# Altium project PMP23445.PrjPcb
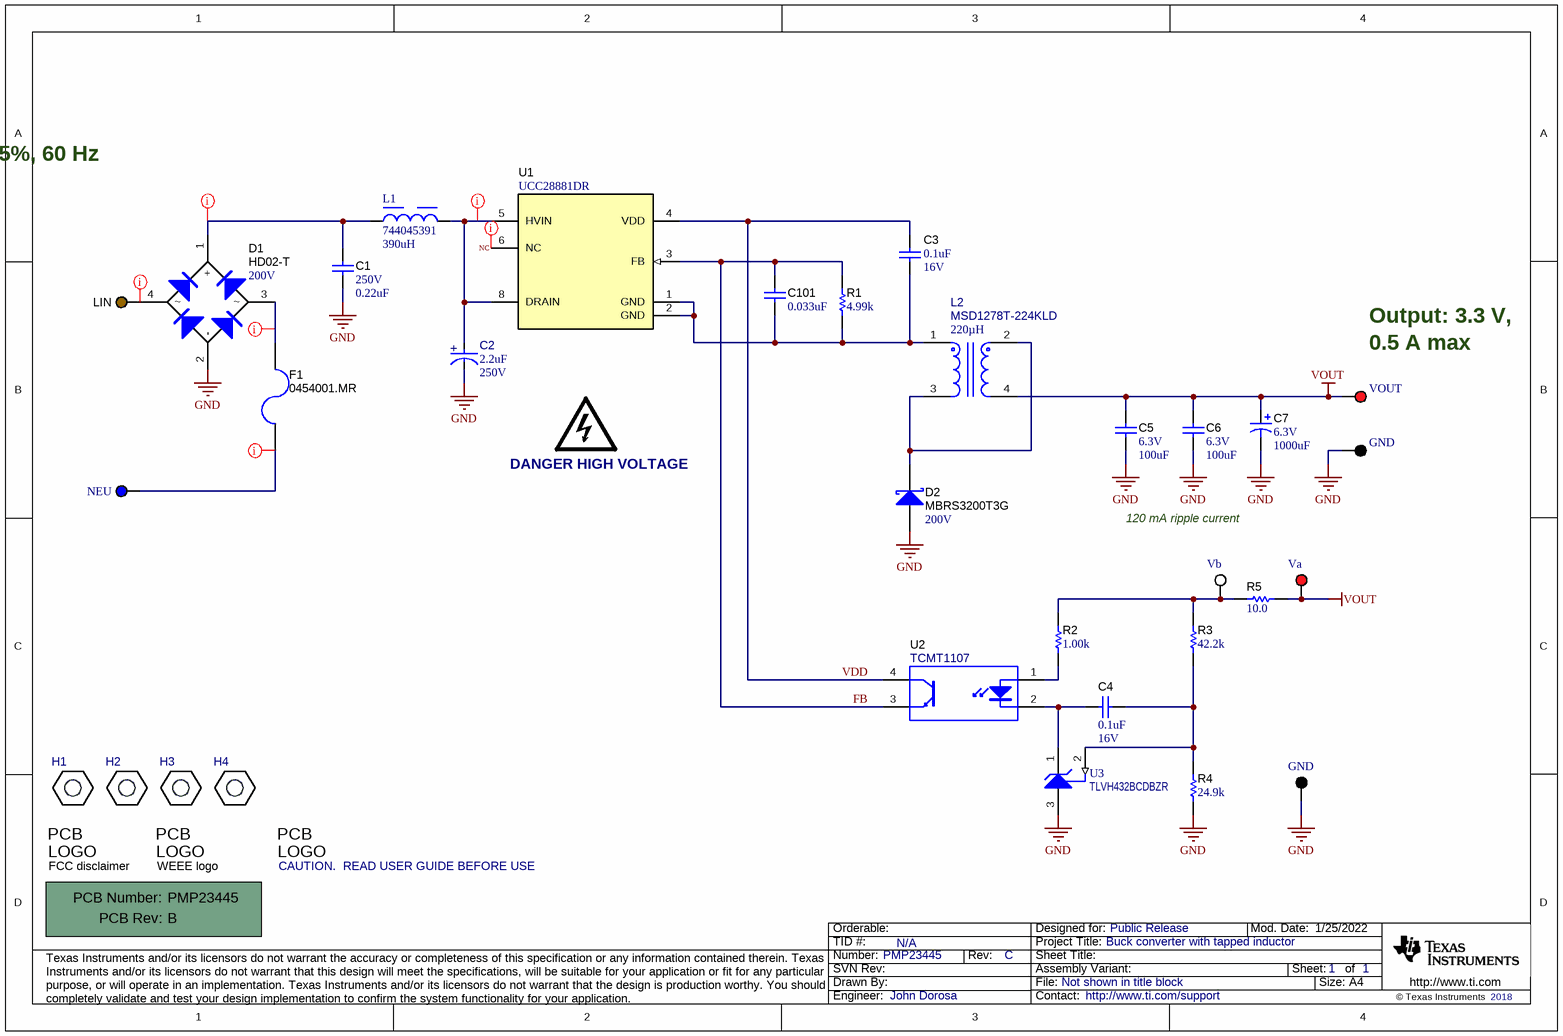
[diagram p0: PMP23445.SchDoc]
TID: N/A; TechSupport: http://www.ti.com/support; SCH_Rev: C; PRJ_Title: Buck converter with tapped inductor; PRJ_Number: PMP23445; PRJ_Engineer: John Dorosa; PRJ_Customer: Public Release; PCB_Rev: B; PCB_Layout: John Dorosa; CopyrightYear: 2018
1 sheet, 37 parts. Net scope: global (net labels, ports and power ports of the same name join across sheets).
Board file: PMP23445.PcbDoc

## Sheet PMP23445.SchDoc
size A4; Date: Not shown in title block; ApprovedBy: Not shown in title block; CheckedBy: Not shown in title block; Author: Not shown in title block; CompanyName: Not shown in title block; Engineer: Not shown in title block; Organization: Not shown in title block; Address1: Not shown in title block; Address2: Not shown in title block; Address3: Not shown in title block; Address4: Not shown in title block; DocumentNumber: 1; Revision: Use project parameter SCH_Rev; SheetNumber: 1; SheetTotal: 1; PageSetup: Record=PageOptions¦CenterHorizontal=True¦CenterVertical=True¦PrintScale=1.00¦XCorrection=1.00¦YCorrection=1.00¦PrintKind=0¦BorderSize=5000000¦LeftOffset=0¦BottomOffset=0¦Orientation=2¦PaperLength=1000¦PaperWidth=1000¦Scale=100¦PaperSource=15¦PrintQuality=600¦MediaType=1¦DitherType=10¦PaperKind=Letter¦PrintScaleMode=1

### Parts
(Parts that share a designator on the sheet are numbered #1, #2 ... from top to bottom, then left to right.)
!PCB1  Printed Circuit Board  (value not drawn)  (mechanical)
C1  VDC_V: 250V  ValueDisplayed: 0.22uF  [CAPRR500W60L780T780H1300]  (hidden comment: B32529D3224J)
C2  ValueDisplayed: 2.2uF  VDC_V: 250V  [FP-ECA2EM2R2_RADIAL-MFG]  (hidden comment: ECA2EM2R2)
C3  value 0.1uF  VDC_V: 16V  [0603]  (hidden comment: GRM188R71C104KA01D)
C4  value 0.1uF  VDC_V: 16V  [0603]  (hidden comment: GRM188R71C104KA01D)
C5  VDC_V: 6.3V  ValueDisplayed: 100uF  [1206_180]  (hidden comment: GRM31CR60J107ME39L)
C6  VDC_V: 6.3V  ValueDisplayed: 100uF  [1206_180]  (hidden comment: GRM31CR60J107ME39L)
C7  VDC_V: 6.3V  ValueDisplayed: 1000uF  [NHG_800x1150]  (hidden comment: ECA-0JHG102)
C101  value 0.033uF  [0603]  (hidden comment: GRM188R71C333KA01D)
D1  HD02-T  value 200V  [MiniDIP]
D2  MBRS3200T3G  value 200V  [SMB]
F1  0454001.MR  [SloBlo452]
GND#1  5011  [Keystone5011]  (value not drawn)
GND#2  5011  [Keystone5011]  (value not drawn)
H1  4824  [KEYSTONE_4824]  (value not drawn)
H2  4824  [KEYSTONE_4824]  (value not drawn)
H3  4824  [KEYSTONE_4824]  (value not drawn)
H4  4824  [KEYSTONE_4824]  (value not drawn)
L1  744045391  Inductance: 390uH  [WE-LQ_1812]
L2  MSD1278T-224KLD  Ind_H: 220µH  [FP-MSD1278T-224KLD_SMT_IND_12MM3_12MM3-MFG]
LIN  5125  [Keystone5125]  (value not drawn)
Logo1  FCC disclaimer  [FCC_disclaimer]  (no BOM)
Logo2  WEEE logo  [WEEE_Minimum]  (no BOM)
Logo3  CAUTION.  READ USER GUIDE BEFORE USE  [IEC_Caution_Small]  (no BOM)
LOGO4  DANGER HIGH VOLTAGE  [IEC_HighVoltage_Small]  (no BOM)
NEU  5127  [Keystone5127]  (value not drawn)
R1  ValueDisplayed: 4.99k  [0603]  (hidden comment: CRCW06034K99FKEAC)
R2  ValueDisplayed: 1.00k  [0603]  (hidden comment: CRCW06031K00FKEA)
R3  ValueDisplayed: 42.2k  [0603]  (hidden comment: CRCW060342K2FKEA)
R4  ValueDisplayed: 24.9k  [0603]  (hidden comment: CRCW060324K9FKEA)
R5  ValueDisplayed: 10.0  [0603]  (hidden comment: CRCW060310R0FKEA)
U1  UCC28881DR  [D0007A_N]
U2  TCMT1107  [SOP-4]
U3  TLVH432BCDBZR  [DBZ0003A_N]
Va  5010  [Keystone5010]  (value not drawn)
Vb  5012  [Keystone5012]  (value not drawn)
VOUT  5010  [Keystone5010]  (value not drawn)

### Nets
GND: C1.2 C2.1(CATHODE) C5.2 C6.2 C7.2(-) D1.2(-) D2.2(A) GND#1.1 GND#2.1 R4.1 U3.3(ANODE)
VOUT: C5.1 C6.1 C7.1(+) L2.4 R5.2 Va.1 VOUT.1
FB: C101.1 R1.2 U1.3(FB) U2.3(E)
NC: U1.6(NC)
VDD: C3.1 U1.4(VDD) U2.4(C)
NetC1_1: C1.1 D1.1(+) L1.1
NetC2_2: C2.2(ANODE) L1.2 U1.5(HVIN) U1.8(DRAIN)
NetC3_2: C3.2 C101.2 L2.1 R1.1 U1.1(GND) U1.2(GND)
NetC4_1: C4.1 U2.2(K) U3.1(CATHODE)
NetC4_2: C4.2 R3.1 R4.2 U3.2(REF)
NetD1_3: D1.3 F1.1
NetD1_4: D1.4 LIN.1
NetD2_1: D2.1(K) L2.2 L2.3
NetF1_2: F1.2 NEU.1
NetR2_1: R2.1 U2.1(A)
NetR2_2: R2.2 R3.2 R5.1 Vb.1

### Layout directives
net class HV: NC, NetC1_1, NetC2_2, NetD1_3, NetD1_4, NetF1_2

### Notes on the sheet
- Input: 120 Vac +/- 15%, 60 Hz
- Output: 3.3 V,
- (near VOUT) 0.5 A max
- 120 mA ripple current

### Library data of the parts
!PCB1 = CMP-0003618-2: Manufacturer: Any; PartNumber: PMP23445
C1 = CMP-0012341-3: CAP, Film, 0.22 uF, 250 V, +/- 5%, TH; Manufacturer: TDK; TaMin_C: -55°C; Polarized: N; SizeAreaWB_mm2: 96.04; Value1: Unknown; Value: 0.22uF; TaMax_C: 125°C; SizeZ_mm: 13; SizeX_mm: 7.8; Cap_Case: 7.8x13x7.8; SizeArea_mm2: 60.84; Cap_F: 220nF; AEC Category: Q200
C2 = CMP-0120186-1: Aluminum Electrolytic Capacitors (Radial Lead Type) 2.2uF ±20% 250V; Manufacturer: Panasonic; AEC Qualified: No; Cap_F: 2.2µF; IRMS_A: 50mA; SizeZ_mm: 12.2mm; Dissipation Factor: 18%; Leakage Current: 43uA; Life: 2000Hours; Value: 2.2µF
C3 C4 = CMP-0007378-5: CAP, CERM, 0.1 uF, 16 V, +/- 10%, X7R, 0603; Manufacturer: MuRata; TaMin_C: -55°C; Polarized: N; SizeAreaWB_mm2: 4.68; Value1: Unknown; U/M: EA; TaMax_C: 125°C; SizeZ_mm: 1; SizeX_mm: 1.6; SizeY_mm: 0.8; SizeArea_mm2: 1.28; Cap_F: 100nF; AEC Category: Q200
C5 C6 = CMP-0008934-2: CAP, CERM, 100 uF, 6.3 V, +/- 20%, X5R, 1206; Manufacturer: MuRata; TaMin_C: -55°C; ESR_ohm: 3m; Polarized: N; SizeAreaWB_mm2: 10.92; Value1: 0.003 ohm; U/M: EA; Value: 100uF; TaMax_C: 85°C; SizeZ_mm: 1.8; SizeX_mm: 3.2; SizeY_mm: 1.6; Cap_Case: 1206; SizeArea_mm2: 5.12; Cap_F: 100µF; AEC Category: Q200
C7 = CMP-0010321-1: CAP, AL, 1000 uF, 6.3 V, +/- 20%, TH; Manufacturer: Panasonic; TaMin_C: -55°C; Polarized: Y; SizeAreaWB_mm2: 100; Value1: Unknown; U/M: EA; Value: 1000uF; TaMax_C: 105°C; SizeZ_mm: 13; SizeX_mm: 8; Cap_Case: 8x11.5mm; SizeArea_mm2: 64; CompType: Capacitor; AEC Qualified: N; Cap_F: 1mF; IRMS_A: 380mA; AEC Category: Q200
C101 = CMP-0007392-5: CAP, CERM, 0.033 uF, 16 V, +/- 10%, X7R, 0603; Manufacturer: MuRata; TaMin_C: -55°C; Polarized: N; SizeAreaWB_mm2: 4.68; Value1: Unknown; U/M: EA; TaMax_C: 125°C; SizeZ_mm: 1; SizeX_mm: 1.6; SizeY_mm: 0.8; Value2: 16V; SizeArea_mm2: 1.28; Cap_F: 33nF; AEC Category: Q200
D1 = CMP-0029216-3: Diode, Switching-Bridge, 200 V, 0.8 A, MiniDIP; Manufacturer: Diodes Inc.; Io_A: 800mA; Value1: 0.8A; Green_Lifecycle: Not Set; SizeArea_mm2: 34.3; Vf_V: 1V; SizeZ_mm: 3; SizeAreaWB_mm2: 62.1; SizeY_mm: 4.9; Green_REACh: Incomplete; AEC Category: Q101; SizeX_mm: 7; TJmax_C: 150°C
D2 = CMP-0028599-2: Diode, Schottky, 200 V, 3 A, SMB; Manufacturer: ON Semiconductor; Io_A: 3A; SizeY_mm: 3.81; RJC_CperW: 62; SizeX_mm: 5.6; TJmax_C: 175°C; Vf_V: 840mV; SizeZ_mm: 2.6; Green_REACh: Incomplete; Green_Lifecycle: Not Set; AEC Category: Q101; SizeAreaWB_mm2: 44.156; Value2: 0.84V; SizeArea_mm2: 21.336
F1 = CMP-0003483-2: Fuse, 1 A, 125VAC/VDC, SMD; Manufacturer: Littelfuse; Irating_A: 1A; Interrupt_AC: 50A; VAC_V: 125V; Rtyp_Ohm: 0.225; MeltingTyp: 1.98
GND#1 GND#2 = CMP-0055148-2: Test Point, Multipurpose, Black, TH; Manufacturer: Keystone Electronics; CNHeader: FALSE; ContactFinish: Silver; Green_REACh: Passed; Green_Lifecycle: Active; CT: TRUE
H1-H4 = CMP-0003690-1: Manufacturer: Keystone; CompType: Standoff
L1 = CMP-0073803-1: WE-LQ SMT Power Inductor, size 1812, 390uH, 0.11A; Manufacturer: Wurth Elektronik; Case/Size Code: 1812; DC Resistance Max: 13Ohm; Q Factor: 50; Saturation Current: 0.27A; Self Resonant Frequency: 5MHz
L2 = CMP-0120188-1: Coupled Inductors 220uH Shld 10% 1.05A 690mOhms AECQ2; Manufacturer: Coilcraft; AEC Grade: Grade 1; AEC Qualified: Yes; DCR_ohm: 0.69; Imax_A: 740mA; Isat: 1.9A; Material: Ferrite; SizeZ_mm: 8.05mm; Self Resonant Frequency: 3.4MHz; Shrouded: true; TaMax_C: +125°C; TaMin_C: -40°C; Test Frequency: 100kHz
LIN = CMP-0055157-1: Test Point, Multipurpose, Brown, TH; Manufacturer: Keystone; CNHeader: FALSE; Green_Lifecycle: Active; Green_REACh: Passed; ContactFinish: Silver; CT: TRUE
Logo1 = CMP-0074847-1: FCC_disclaimer; Library Reference: Logo
Logo2 = CMP-0074769-1
Logo3 = CMP-0074836-1: IEC 61010-1 Caution Warning; SymbolCreator: a0412235; Lib Reference: IEC_Caution
LOGO4 = CMP-0074835-1: IEC 61010-1 High Voltage Warning; SymbolCreator: a0412235
NEU = CMP-0055156-1: Test Point, Multipurpose, Blue, TH; Manufacturer: Keystone; CNHeader: FALSE; Green_Lifecycle: Active; Green_REACh: Passed; ContactFinish: Silver; CT: TRUE
R1 = CMP-0082533-1: RES, 4.99 k, 1%, 0.1 W, 0603; Manufacturer: Vishay-Dale; Power_W: 100mW; TempCo: 100 ppm/C; SizeAreaWB_mm2: 4.68; Value_Code: 4k99; Value: 4.99k; EIA_Code: E96; SizeX_mm: 1.6; SizeY_mm: 0.8; SizeZ_mm: 1; Value2: 0.1W; SizeArea_mm2: 1.28; AEC Qualified: N; VDC_V: 75V; AEC Category: Q200
R2 = CMP-0022109-5: RES, 1.00 k, 1%, 0.1 W, AEC-Q200 Grade 0, 0603; Manufacturer: Vishay-Dale; Power_W: 100mW; TempCo: 100 ppm/C; Value_Code: 1k00; Value: 1.00k; EIA_Code: E96; Res_ohm: 1k; SizeX_mm: 1.6; SizeY_mm: 0.8; SizeZ_mm: 1; Value2: 0.1W; SizeArea_mm2: 1.28; AEC Qualified: Y; VDC_V: 75V; AEC Category: Q200; AEC Grade: 0
R3 = CMP-0022418-4: RES, 42.2 k, 1%, 0.1 W, AEC-Q200 Grade 0, 0603; Manufacturer: Vishay-Dale; Power_W: 100mW; TempCo: 100 ppm/C; Value_Code: 42k2; Value: 42.2k; EIA_Code: E96; SizeX_mm: 1.6; SizeY_mm: 0.8; SizeZ_mm: 1; Value2: 0.1W; SizeArea_mm2: 1.28; AEC Qualified: Y; VDC_V: 75V; AEC Category: Q200; AEC Grade: 0
R4 = CMP-0022237-4: RES, 24.9 k, 1%, 0.1 W, AEC-Q200 Grade 0, 0603; Manufacturer: Vishay-Dale; Power_W: 100mW; TempCo: 100 ppm/C; Value_Code: 24k9; Value: 24.9k; EIA_Code: E96; SizeX_mm: 1.6; SizeY_mm: 0.8; SizeZ_mm: 1; Value2: 0.1W; SizeArea_mm2: 1.28; AEC Qualified: Y; VDC_V: 75V; AEC Category: Q200; AEC Grade: 0
R5 = CMP-0022003-4: RES, 10.0, 1%, 0.1 W, AEC-Q200 Grade 0, 0603; Manufacturer: Vishay-Dale; Power_W: 100mW; TempCo: 100 ppm/C; Value_Code: 10R0; Value: 10.0; EIA_Code: E96; Res_ohm: 10; SizeX_mm: 1.6; SizeY_mm: 0.8; SizeZ_mm: 1; Value2: 0.1W; SizeArea_mm2: 1.28; AEC Qualified: Y; VDC_V: 75V; AEC Category: Q200; AEC Grade: 0
U1 = CMP-0074092-2: 700-V Lowest Quiescent Current Off-Line Switcher, D0007A (SOIC-7); Alternate Manufacturer: Texas Instruments; SizeAreaWB_mm2: 55.2; U/M: EA; SizeZ_mm: 1.75; SizeX_mm: 6.0; SizeY_mm: 4.9; SizeArea_mm2: 29.4; CompType: IC; AEC Category: Q200; AEC Qualified: N
U2 = CMP-0006166-3: Optocoupler, 3.75 kV, 80-160% CTR, SMT; Manufacturer: Vishay-Semiconductor; CTR (Max): 160%; SizeAreaWB_mm2: 43.65; CTR (Min): 80%; SizeZ_mm: 2.3; SizeX_mm: 7; SizeY_mm: 2.85; SizeArea_mm2: 19.95; Voltage_Isolation_Vrms: 3.75kV
U3 = CMP-0033010-1: Low-Voltage Adjustable Precision Shunt Regulator, 129 ppm / degC, 80 mA, 0 to 70 degC, 3-pin SOT-23 (DBZ), Green (RoHS & no Sb/Br); Manufacturer: Texas Instruments; SubFamily: Shunt Voltage Reference; VO Adj(Min)(V): 1.24; Iout/Iz(Max)(mA): 80; Initial Accuracy @ 25/deg C(%): 0.5; VO Adj(Max)(V): 18; Rating: Catalog; Temp Coeff(Max)(ppm/ degree C): 129
Va VOUT = CMP-0055147-2: Test Point, Multipurpose, Red, TH; Manufacturer: Keystone Electronics; CT: TRUE; ContactFinish: Silver; Green_Lifecycle: Active; CNHeader: FALSE; Green_REACh: Passed
Vb = CMP-0055149-2: Test Point, Multipurpose, White, TH; Manufacturer: Keystone Electronics; ContactFinish: Silver; CT: TRUE; CNHeader: FALSE; Green_Lifecycle: Active; Green_REACh: Passed

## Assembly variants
001: not fitted FID1 FID2 FID3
